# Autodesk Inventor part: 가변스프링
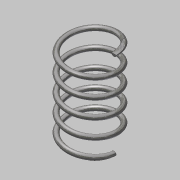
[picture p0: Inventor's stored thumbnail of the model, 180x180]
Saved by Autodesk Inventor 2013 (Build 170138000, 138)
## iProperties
Created: 2019-05
Part Number: 가변스프링
Material: 스테인리스강
Document SubType Name: Modeling
Designer: Administrator
Density: 8.08 g/cm^3
Mass: 7.86239 g
Surface Area: 19.733 cm^2
Volume: 0.973069 cm^3
Author: Administrator
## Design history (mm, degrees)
sketch "스케치1"
  geometry: L1 (0, 0)-(10, 0); L2 (10, 0)-(10, 34); L3 (10, 34)-(0, 34); L4 (0, 34)-(0, 0); C1 r 1 at (10, 0)
  constraints: 8 end point, 2 parallel, 1 centre point, 1 coincident, 1 horizontal, 1 perpendicular
  dimensions: "d0" = 2 diameter of C1; "d2" = 34 distance of L1.end L2.end (derived); "d3" = 20 diameter of L2 L4
feature "코일1" sketch "스케치1" pitch "d4" = 10; turns "d6" = 5; dims "d5" = 34 (= d2), "d7" = 0, angle "d8" = 90 deg, angle "d9" = 90 deg, "d10" = 0, "d11" = 0
sketch "스케치2"
  geometry: L1 (34, 11.5)-(0, 11.5); L2 (0, 11.5)-(0, -11.5); L3 (0, -11.5)-(34, -11.5); L4 (34, -11.5)-(34, 11.5); 2 further points
  constraints: 8 end point, 2 parallel, 1 coincident, 1 horizontal, 1 midpoint, 1 perpendicular
  dimensions: "d12" = 34 distance of L2.end L3.end (derived); "d14" = 23 distance between parallel lines of L3 L1
extrude "돌출1" sketch "스케치2" stored distance "d15" = 23; taper "d16" = 0 deg
node "솔리드1"
